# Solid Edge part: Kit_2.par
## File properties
Username: ahadarics
Dokumentum tartalom típus: 0
Author: ahadarics
Last saved by: psaghy
Revision: 78
Sűrűség: 0,000 kg/m^3
Pontosság: 0,990
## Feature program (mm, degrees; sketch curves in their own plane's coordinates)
base feature "unnamed BaseFeature 1"
sketch for "Furat_1" plane through (0, -3, 8.5) normal (0, 0, 1) x-axis (0, 1, 0)
  hole centre (-0.5, 0) bore radius 2.067
hole "Furat_1" nominal diameter 5 finite  ThreadDepth = 4.5 mm
chamfer "Letörés_1" setback 0.5
sketch for "Kihúzás_2" #1 plane through (0, 19.5, 0) normal (0, 1, 0) x-axis (0, 0, -1)
  arc centre (0, 0) radius 8 from (5.2915, -6) to (-5.2915, -6) cw
  line (-5.2915, -6) -> (5.2915, -6)
sketch for "Kihúzás_2" #2 plane through (0, 19.5, 0) normal (0, 1, 0) x-axis (0, 0, -1)
  line (-5.2915, 6) -> (5.2915, 6)
extrude "Kihúzás_2" add finite 13.84 along -normal
thread "unnamed Thread 1"
sketch for "Kivágás_1" #1 plane through (0, 19.5, 0) normal (0, 1, 0) x-axis (0, 0, -1)
  line (-5.2915, -6) -> (5.2915, -6)
  arc centre (0, 0) radius 8 from (5.2915, -6) to (-5.2915, -6) cw
sketch for "Kivágás_1" #2 plane through (0, 19.5, 0) normal (0, 1, 0) x-axis (0, 0, -1)
  line (-5.2915, 6) -> (5.2915, 6)
extrude "Kivágás_1" cut finite 13.85 along -normal
chamfer "Letörés_2" setback 1
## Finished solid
Body 1: solid body, 32 faces, 71 edges, 40 vertices.
  Faces by surface: plane 13, cylinder 11, cone 8
  Edges by curve: line 32, circle 31, intersection 4, spline 4
Bounding box of the edges (mm): 19.000 x 28.500 x 18.000, from (-9.5, -9, -9.5) to (9.5, 19.5, 8.5).
Cylindrical faces by radius (mm): R2.055 x1, R2.067 x1, R3 x1, R6.6 x1, R6.85 x2, R8 x4, R9.5 x1
Conical faces (half-angle, radius in mm at the cone's reference point): 45 deg R2.567 x1, 45 deg R3.1 x2, 45 deg R8 x2, 59 deg R1.0335 x1, 60 deg R7.425 x2
Planar faces by outward normal: +x 1, +y 7, +z 2, -x 1, -y 2
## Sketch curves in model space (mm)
arc centre (0, 19.5, 0) radius 8 from (6, 19.5, -5.2915) through (7.9967, 19.5, 0.2312) to (6, 19.5, 5.2915)
line (6, 19.5, 5.2915) -> (6, 19.5, -5.2915)
arc centre (0, 19.5, 0) radius 8 from (-6, 19.5, 5.2915) through (-7.9967, 19.5, -0.2312) to (-6, 19.5, -5.2915)
line (-6, 19.5, 5.2915) -> (-6, 19.5, -5.2915)
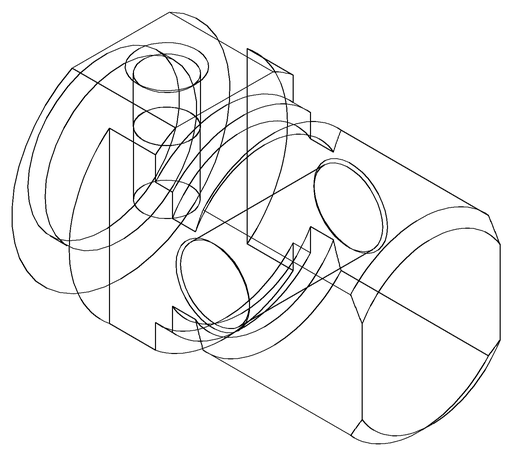
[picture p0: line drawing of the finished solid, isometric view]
